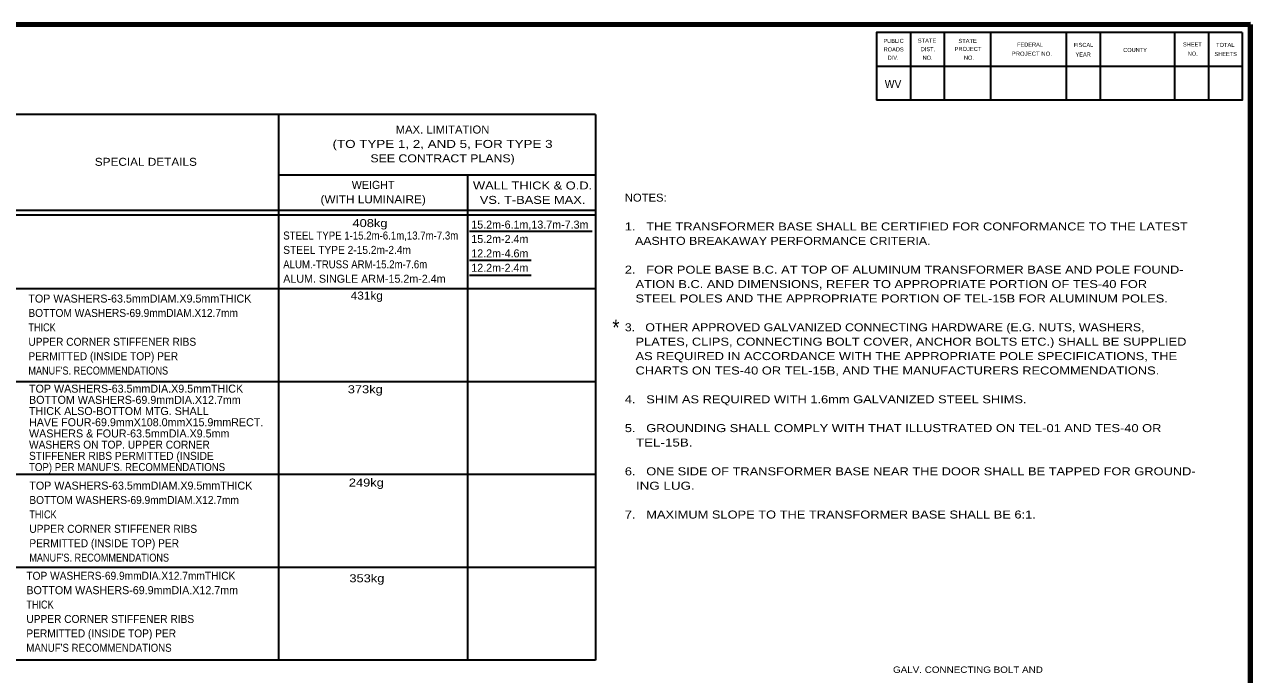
# Model space of a CAD drawing. Extents: x -1228 to -372, y 190 to 734.
# Drawn here: x -838.1 to -378.5, y 483.7 to 727.3 of the extents above; entities that cross this region are included whole.
import ezdxf
from ezdxf.enums import TextEntityAlignment as Align

# ---------------------------------------------------------------- set-up
doc = ezdxf.new("R2010")
doc.units = 0
doc.header["$LTSCALE"] = 1.2
doc.layers.add('1', color=7, linetype='Continuous', lineweight=25)
doc.layers.add('61', color=7, linetype='Continuous', lineweight=35)

msp = doc.modelspace()

# ---------------------------------------------------------------- linework, layer by layer
at = {"layer": '1', "lineweight": 158}
msp.add_line((-378.542, 201.223), (-378.542, 727.323), dxfattribs=at)
at = {"layer": '1', "lineweight": 13}
msp.add_line((-378.542, 201.223), (-378.542, 727.323), dxfattribs=at)
at = {"layer": '1', "lineweight": 35}
for p, q in [((-624.102, 693.614), (-1148.502, 693.614)), ((-742.902, 693.614), (-742.902, 489.014)), ((-624.102, 693.614), (-624.102, 489.014)), ((-624.102, 670.814), (-742.902, 670.814)), ((-672.102, 670.814), (-672.102, 489.014)), ((-624.102, 657.614), (-1148.502, 657.614)), ((-624.102, 655.814), (-1148.502, 655.814)), ((-671.261, 649.803), (-625.298, 649.803)), ((-671.261, 638.951), (-648.19, 638.951)), ((-671.261, 633.323), (-648.19, 633.323)), ((-624.102, 628.214), (-1148.502, 628.214)), ((-624.102, 593.414), (-1148.502, 593.414)), ((-624.102, 558.614), (-1148.502, 558.614)), ((-624.102, 523.814), (-1148.502, 523.814)), ((-624.102, 489.014), (-1148.502, 489.014))]:
    msp.add_line(p, q, dxfattribs=at)
at = {"layer": '1', "lineweight": 158}
msp.add_lwpolyline([(-378.542, 727.323), (-1170.242, 727.223), (-1170.141, 201.223)], dxfattribs=at)
at = {"layer": '61'}
for p, q in [((-506.042, 724.323), (-506.042, 698.923)), ((-493.341, 724.323), (-493.341, 698.923)), ((-475.942, 724.323), (-475.942, 698.923)), ((-447.642, 724.323), (-447.642, 698.923)), ((-434.942, 724.323), (-434.942, 698.923)), ((-407.042, 724.323), (-407.042, 698.923)), ((-394.341, 724.323), (-394.341, 698.923)), ((-381.642, 711.623), (-518.741, 711.623))]:
    msp.add_line(p, q, dxfattribs=at)
for points in [[(-381.642, 724.323), (-518.741, 724.323), (-518.741, 698.923)], [(-381.642, 724.323), (-381.642, 698.923), (-518.741, 698.923)]]:
    msp.add_lwpolyline(points, dxfattribs=at)

# ---------------------------------------------------------------- texts
at = {"layer": '1'}
for s, height, width, p in [('WV', 3.048, 0.95, (-515.642, 703.523)), ('NOTES:', 3, 1.05, (-613.087, 660.922)), ('408kg', 3, 1.2, (-715.177, 651.374)), ('1.   THE TRANSFORMER BASE SHALL BE CERTIFIED FOR CONFORMANCE TO THE LATEST', 3, 1.2, (-613.087, 650.122)), ('STEEL TYPE 1-15.2m-6.1m,13.7m-7.3m', 3, 0.9, (-741.139, 646.721)), ('STEEL TYPE 2-15.2m-2.4m', 3, 0.95, (-741.139, 641.321)), ('   AASHTO BREAKAWAY PERFORMANCE CRITERIA.', 3, 1.15, (-613.087, 644.722)), ('ALUM.-TRUSS ARM-15.2m-7.6m', 3, 0.9, (-741.139, 635.921)), ('2.   FOR POLE BASE B.C. AT TOP OF ALUMINUM TRANSFORMER BASE AND POLE FOUND-', 3, 1.2, (-613.087, 633.922)), ('   ATION B.C. AND DIMENSIONS, REFER TO APPROPRIATE PORTION OF TES-40 FOR', 3, 1.2, (-613.087, 628.522)), ('431kg', 3, 1.1, (-715.836, 624.211)), ('   STEEL POLES AND THE APPROPRIATE PORTION OF TEL-15B FOR ALUMINUM POLES.', 3, 1.2, (-613.087, 623.122)), ('BOTTOM WASHERS-69.9mmDIAM.X12.7mm', 3, 0.95, (-836.677, 617.69)), ('*', 6, 0.85, (-617.756, 610.729)), ('THICK', 3, 0.85, (-836.677, 612.289)), ('3.   OTHER APPROVED GALVANIZED CONNECTING HARDWARE (E.G. NUTS, WASHERS,', 3, 1.15, (-613.087, 612.322)), ('UPPER CORNER STIFFENER RIBS', 3, 0.95, (-836.677, 606.889)), ('   PLATES, CLIPS, CONNECTING BOLT COVER, ANCHOR BOLTS ETC.) SHALL BE SUPPLIED', 3, 1.2, (-613.087, 606.922)), ('PERMITTED (INSIDE TOP) PER', 3, 0.95, (-836.677, 601.49)), ('   AS REQUIRED IN ACCORDANCE WITH THE APPROPRIATE POLE SPECIFICATIONS, THE', 3, 1.2, (-613.087, 601.522)), ("MANUF'S. RECOMMENDATIONS", 3, 0.85, (-836.677, 596.09)), ('   CHARTS ON TES-40 OR TEL-15B, AND THE MANUFACTURERS RECOMMENDATIONS.', 3, 1.2, (-613.087, 596.122)), ('373kg', 3, 1.2, (-716.951, 589.085)), ('4.   SHIM AS REQUIRED WITH 1.6mm GALVANIZED STEEL SHIMS.', 3, 1.2, (-613.087, 585.322)), ('5.   GROUNDING SHALL COMPLY WITH THAT ILLUSTRATED ON TEL-01 AND TES-40 OR', 3, 1.2, (-613.087, 574.522)), ('WASHERS ON TOP. UPPER CORNER', 3, 0.95, (-836.436, 568.321)), ('   TEL-15B.', 3, 1.25, (-613.087, 569.122)), ('STIFFENER RIBS PERMITTED (INSIDE', 3, 0.95, (-836.436, 564.121)), ("TOP) PER MANUF'S. RECOMMENDATIONS", 3, 0.9, (-836.436, 559.921)), ('6.   ONE SIDE OF TRANSFORMER BASE NEAR THE DOOR SHALL BE TAPPED FOR GROUND-', 3, 1.2, (-613.087, 558.322)), ('249kg', 3, 1.2, (-716.546, 554.111)), ('   ING LUG.', 3, 1.25, (-613.087, 552.922)), ('BOTTOM WASHERS-69.9mmDIAM.X12.7mm', 3, 0.95, (-836.32, 547.567)), ('THICK', 3, 0.85, (-836.32, 542.167)), ('7.   MAXIMUM SLOPE TO THE TRANSFORMER BASE SHALL BE 6:1.', 3, 1.2, (-613.087, 542.122)), ('UPPER CORNER STIFFENER RIBS', 3, 0.95, (-836.32, 536.767)), ('PERMITTED (INSIDE TOP) PER', 3, 0.95, (-836.32, 531.367)), ("MANUF'S. RECOMMENDATIONS", 3, 0.85, (-836.32, 525.967)), ('TOP WASHERS-69.9mmDIA.X12.7mmTHICK', 3, 0.95, (-837.433, 519.169)), ('353kg', 3, 1.2, (-716.343, 518.224)), ('THICK', 3, 0.85, (-837.433, 508.369)), ('UPPER CORNER STIFFENER RIBS', 3, 0.95, (-837.433, 502.969)), ('PERMITTED (INSIDE TOP) PER', 3, 0.95, (-837.433, 497.569)), ("MANUF'S RECOMMENDATIONS", 3, 0.9, (-837.433, 492.169)), ('GALV. CONNECTING BOLT AND', 2.4, 1.15, (-512.555, 484.26))]:
    msp.add_text(s, height=height, dxfattribs=dict(at, width=width)).set_placement(p)
for s, width, p in [('MAX. LIMITATION', 1.05, (-681.419, 686.454)), ('(TO TYPE 1, 2, AND 5, FOR TYPE 3', 1.25, (-681.419, 681.054)), ('SPECIAL DETAILS', 1.1, (-792.641, 674.349)), ('SEE CONTRACT PLANS)', 1.15, (-681.419, 675.654)), ('WALL THICK & O.D.', 1.2, (-647.669, 665.477)), ('(WITH LUMINAIRE)', 1.1, (-707.435, 660.304)), ('VS. T-BASE MAX.', 1.2, (-647.669, 660.077))]:
    msp.add_text(s, height=3, dxfattribs=dict(at, width=width)).set_placement(p, align=Align.CENTER)
msp.add_text('WEIGHT', height=3, dxfattribs=at).set_placement((-707.435, 665.704), align=Align.CENTER)
for s, p in [('15.2m-6.1m,13.7m-7.3m', (-670.645, 650.821)), ('15.2m-2.4m', (-670.645, 645.421)), ('12.2m-4.6m', (-670.645, 640.021)), ('12.2m-2.4m', (-670.645, 634.621)), ('ALUM. SINGLE ARM-15.2m-2.4m   ', (-741.139, 630.521)), ('TOP WASHERS-63.5mmDIAM.X9.5mmTHICK', (-836.677, 623.09)), ('TOP WASHERS-63.5mmDIA.X9.5mmTHICK', (-836.436, 589.321)), ('THICK ALSO-BOTTOM MTG. SHALL', (-836.436, 580.921)), ('BOTTOM WASHERS-69.9mmDIA.X12.7mm', (-836.436, 585.121)), ('HAVE FOUR-69.9mmX108.0mmX15.9mmRECT.', (-836.436, 576.721)), ('WASHERS & FOUR-63.5mmDIA.X9.5mm', (-836.436, 572.521)), ('TOP WASHERS-63.5mmDIAM.X9.5mmTHICK', (-836.32, 552.967)), ('BOTTOM WASHERS-69.9mmDIA.X12.7mm', (-837.433, 513.769))]:
    msp.add_text(s, height=3, dxfattribs=at).set_placement(p)
at = {"layer": '61'}
for s, height, rotation, p in [('PUBLIC', 1.525, 0.033, (-516.142, 720.423)), ('ROADS', 1.525, 0.124, (-516.042, 717.223)), ('DIST.', 1.525, 0.056, (-502.142, 717.323)), ('FEDERAL', 1.523, 0.007, (-466.042, 719.023)), ('FISCAL', 1.525, 359.942, (-444.841, 718.923)), ('COUNTY', 1.523, 0.069, (-426.242, 717.023)), ('SHEET', 1.525, 0.059, (-403.841, 719.123)), ('SHEETS', 1.523, 359.959, (-392.042, 715.523)), ('DIV.', 1.525, 359.932, (-514.542, 714.123)), ('YEAR', 1.523, 0.105, (-444.142, 715.323))]:
    msp.add_text(s, height=height, rotation=rotation, dxfattribs=at).set_placement(p)
for s, rotation, width, p in [('STATE', 0.059, 1.05, (-503.242, 720.523)), ('STATE', 0.059, 1.05, (-488.042, 720.423)), ('PROJECT', 359.908, 1.05, (-489.442, 717.423)), ('PROJECT NO.', 359.922, 1.1, (-468.042, 715.623)), ('NO.', 359.852, 0.9, (-402.042, 715.623)), ('TOTAL', 359.926, 1.05, (-391.442, 718.923)), ('NO.', 359.852, 0.9, (-501.442, 714.123)), ('NO.', 0.225, 0.9, (-485.942, 714.123))]:
    msp.add_text(s, height=1.525, rotation=rotation, dxfattribs=dict(at, width=width)).set_placement(p)

doc.saveas('drawing.dxf')
